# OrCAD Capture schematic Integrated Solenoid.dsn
size D
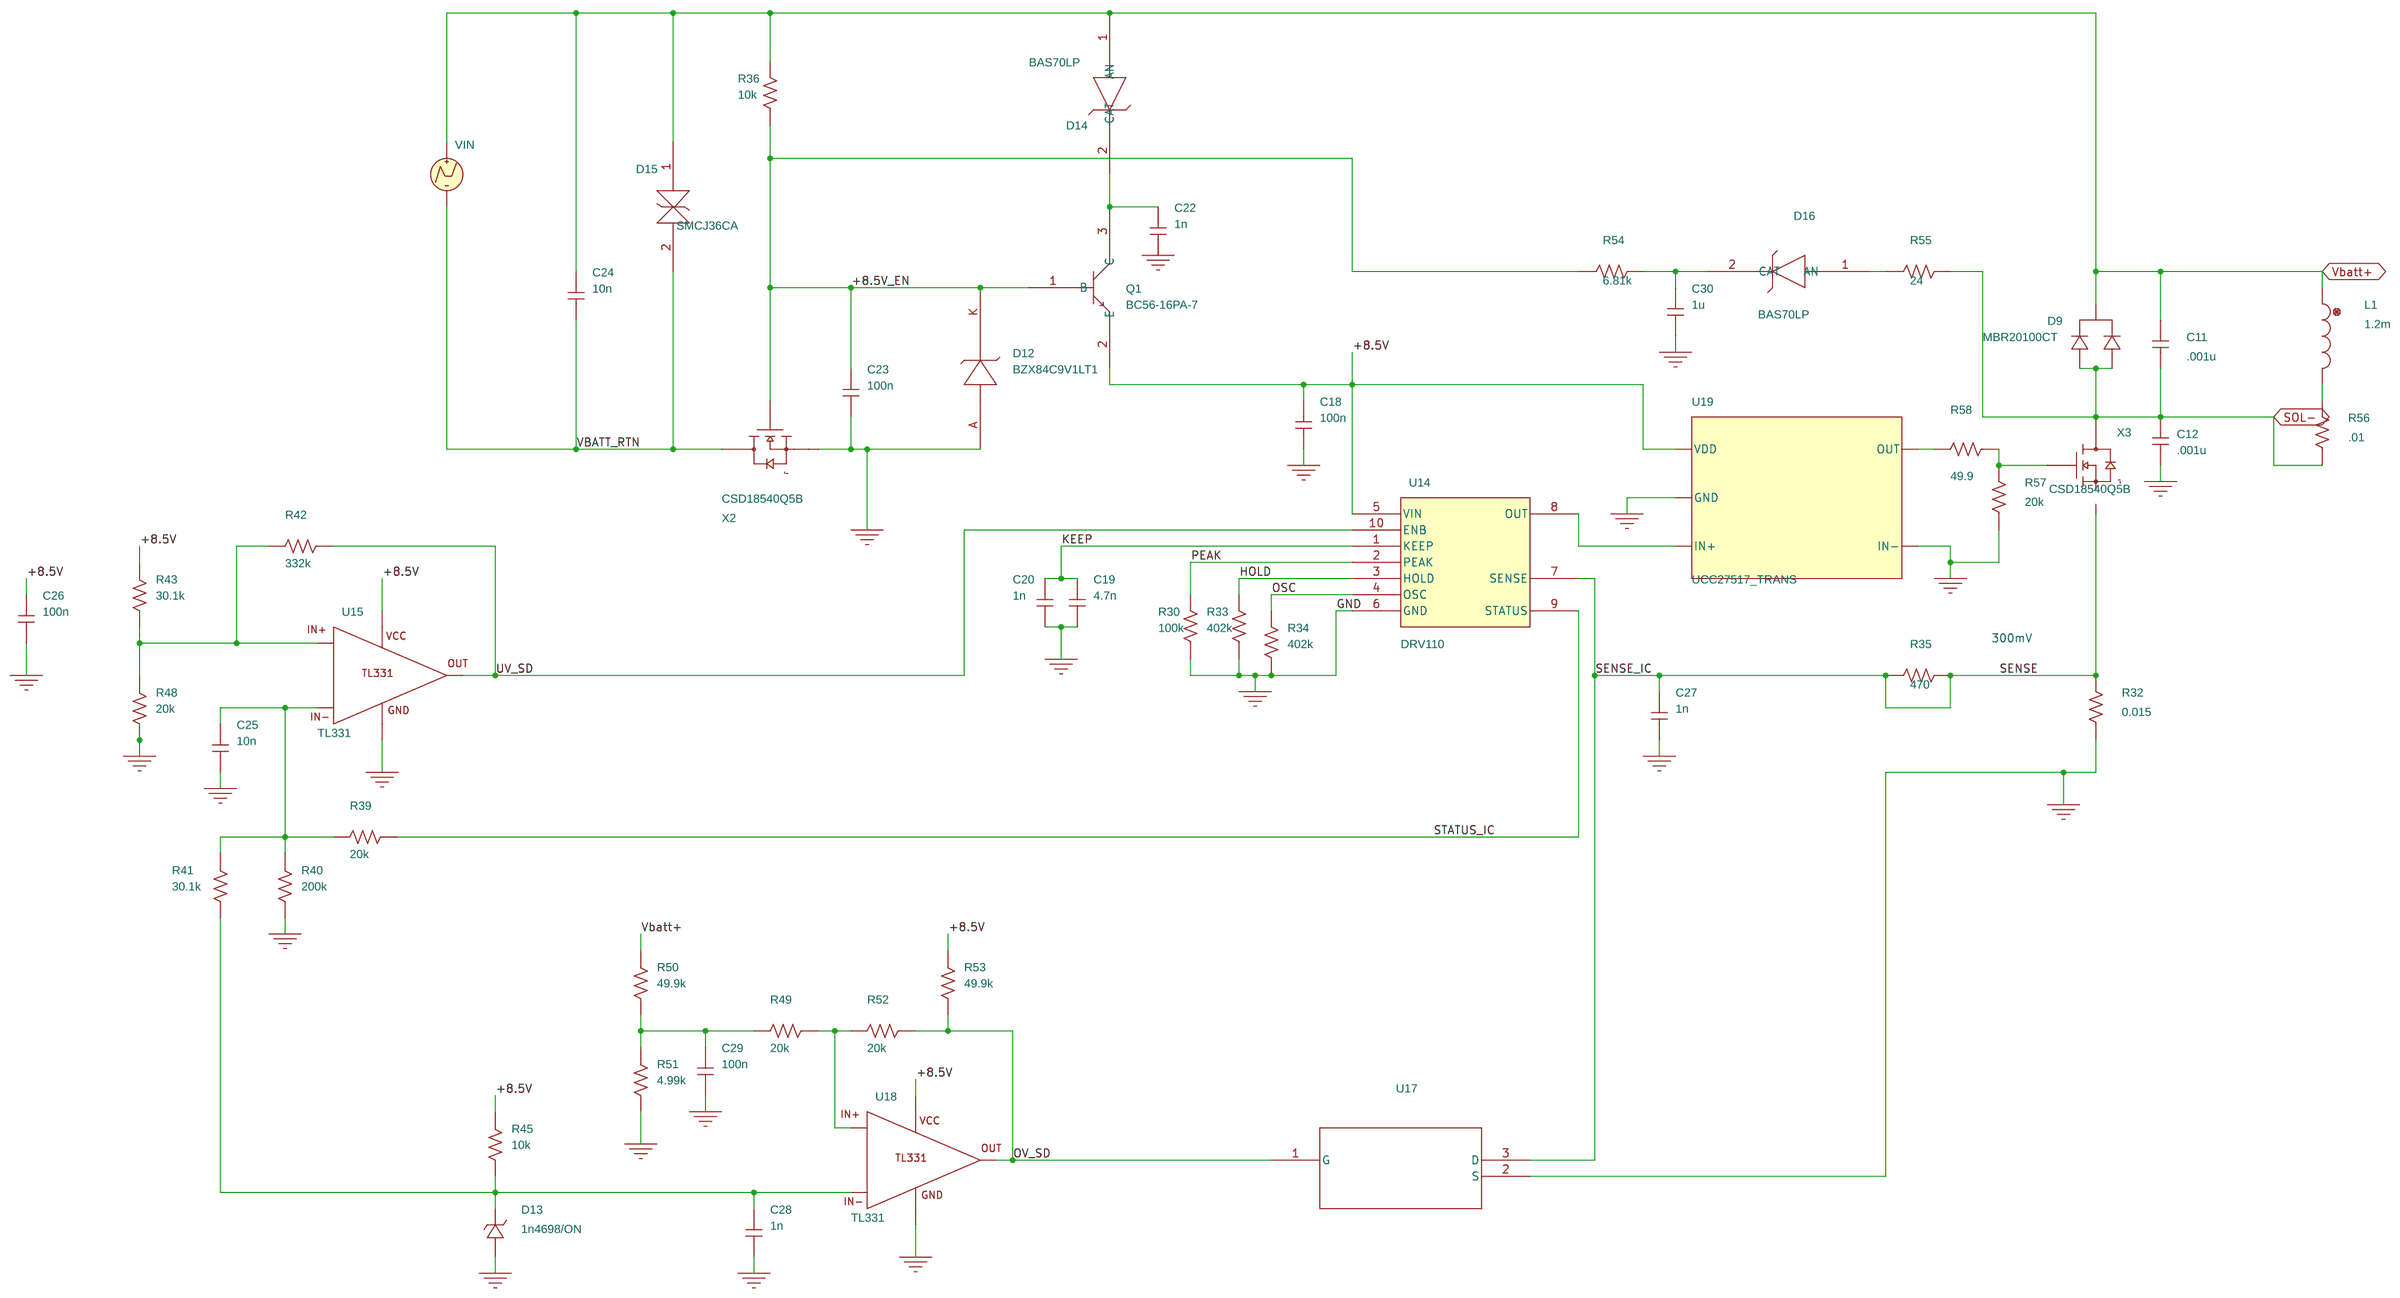
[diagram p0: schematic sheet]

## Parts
C11  .001u  [RAD/CK05]
C12  .001u  [RAD/CK05]
C18  100n  [RAD/CK05]
C19  4.7n  [RAD/CK05]
C20  1n  [RAD/CK05]
C22  1n  [RAD/CK05]
C23  100n  [RAD/CK05]
C24  10n  [RAD/CK05]
C25  10n  [RAD/CK05]
C26  100n  [RAD/CK05]
C27  1n  [RAD/CK05]
C28  1n  [RAD/CK05]
C29  100n  [RAD/CK05]
C30  1u  [RAD/CK05]
D9  MBR20100CT  [357C-03]
D12  BZX84C9V1LT1
D13  1n4698/ON
D14  BAS70LP
D15  SMCJ36CA
D16  BAS70LP
L1  1.2m  [DISC/.350x.175/LS.200x.100/.034]
Q1  BC56-16PA-7  [DFN]
R30  100k  [AX/RC05]
R32  0.015  [AX/RC05]
R33  402k  [AX/RC05]
R34  402k  [AX/RC05]
R35  470  [AX/RC05]
R36  10k  [AX/RC05]
R39  20k  [AX/RC05]
R40  200k  [AX/RC05]
R41  30.1k  [AX/RC05]
R42  332k  [AX/RC05]
R43  30.1k  [AX/RC05]
R45  10k  [AX/RC05]
R48  20k  [AX/RC05]
R49  20k  [AX/RC05]
R50  49.9k  [AX/RC05]
R51  4.99k  [AX/RC05]
R52  20k  [AX/RC05]
R53  49.9k  [AX/RC05]
R54  6.81k  [AX/RC05]
R55  24  [AX/RC05]
R56  .01  [AX/RC05]
R57  20k  [AX/RC05]
R58  49.9  [AX/RC05]
U14  DRV110
U15  TL331
U17  Value  [SOT-323]
U18  TL331
U19  UCC27517_TRANS
VIN  VPWL
X2  CSD18540Q5B
X3  CSD18540Q5B

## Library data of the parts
C11 = C: AppProp: InductiveSlave:;SRF:;PrevCap:1u;PrevESL:; IC: 0; Tolerance: 10
C12 = C: AppProp: InductiveSlave:;SRF:;PrevCap:.001u;PrevESL:; IC: 0; Tolerance: 10
C18-C20 C22-C30 = C
D9 = MBR20035CT
D12 = BZX84C9V1LT1_0: PSpiceTemplate: X^@REFDES %A %K @MODEL
D13 = 1n4698_ON
D14 D16 = BAS70LP_1
D15 = SMCJ36CA_1: PSpiceTemplate: D^@REFDES %1 %2 @MODEL ?AREA/@AREA/
L1 = L
Q1 = BC56-16PA-7
R30 R32-R36 R39-R43 R45 R48-R58 = R
U14 = DRV110_1
U15 U18 = TL331: PSpiceTemplate: X^@REFDES %OUT %IN+ %IN- %VCC %GND @MODEL
U17 = BSS138W-7-F: PSpiceTemplate: X^@REFDES %S %G %D @MODEL
U19 = UCC27517_TRANS
VIN = VPWL: PSpiceTemplate: V^@REFDES %+ %- ?DC|DC @DC| ?AC|AC @AC|\n+PWL @T1 @V1 @T2 @V2 #T3/@T3 @V3/ #T4/@T4 @V4/ #T5/@T5 @V5/ #T6/@T6 @V6/ #T7/@T7 @V7/ #T8/@T8 @V8/ #T9/@T9 @V9/ #T10/@T10 @V10/; T1: 0; T2: 1.00m; V1: 0; V2: 12
X2 = CSD18540Q5B_0
X3 = CSD18540Q5B

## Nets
+8.5V: C18.2 C26.2 Q1.2(E) R43.1 R45.1 R53.1 U14.5(VIN) U15.4(VCC) U18.4(VCC) U19.VDD
+8.5V_EN: C23.2 D12.K Q1.1(B) R36.1 R54.1 X2.gate
Vbatt+: C11.2 C24.2 D9.3 D14.1(AN) D15.1 L1.1 R36.2 R50.1 VIN.1(+)
VBATT_RTN: C24.1 D15.2 VIN.2(-) X2.drain
0: C12.1 C18.1 C19.1 C20.1 C22.1 C23.1 C25.1 C26.1 C27.1 C28.1 C29.1 C30.1 D12.A D13.0(1) R30.1 R32.1 R33.1 R34.1 R40.2 R48.2 R51.2 R57.1 U14.6(GND) U15.5(GND) U17.2(S) U18.5(GND) U19.GND U19.IN- X2.source
HOLD: R33.2 U14.3(HOLD)
KEEP: C19.2 C20.2 U14.1(KEEP)
OSC: R34.2 U14.4(OSC)
OV_SD: R52.1 R53.2 U17.1(G) U18.1(OUT)
PEAK: R30.2 U14.2(PEAK)
SENSE: C27.2 R32.2 R35.1 R35.2 U14.7(SENSE) U17.3(D) X3.source
SOL-: C11.1 C12.2 D9.1 D9.2 R55.2 R56.1 X3.drain
STATUS_IC: R39.1 U14.9(STATUS)
UV_SD: R42.1 U14.10(ENB) U15.1(OUT)
N16834473: C22.2 D14.2(CAT) Q1.3(C)
N16836970: C25.2 R39.2 R40.1 R41.1 U15.3(IN-)
N16837143: R42.2 R43.2 R48.1 U15.2(IN+)
N16838091: C28.2 D13.1(2) R41.2 R45.2 U18.3(IN-)
N16838611: C29.2 R49.2 R50.2 R51.1
N16838776: R49.1 R52.2 U18.2(IN+)
N16843699: D16.1(AN) R55.1
N16843702: C30.2 D16.2(CAT) R54.2
N16848989: L1.2 R56.2
N16859215: U14.8(OUT) U19.IN+
N16859571: R58.2 U19.OUT
N16859574: R57.2 R58.1 X3.gate

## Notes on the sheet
- 300mV
